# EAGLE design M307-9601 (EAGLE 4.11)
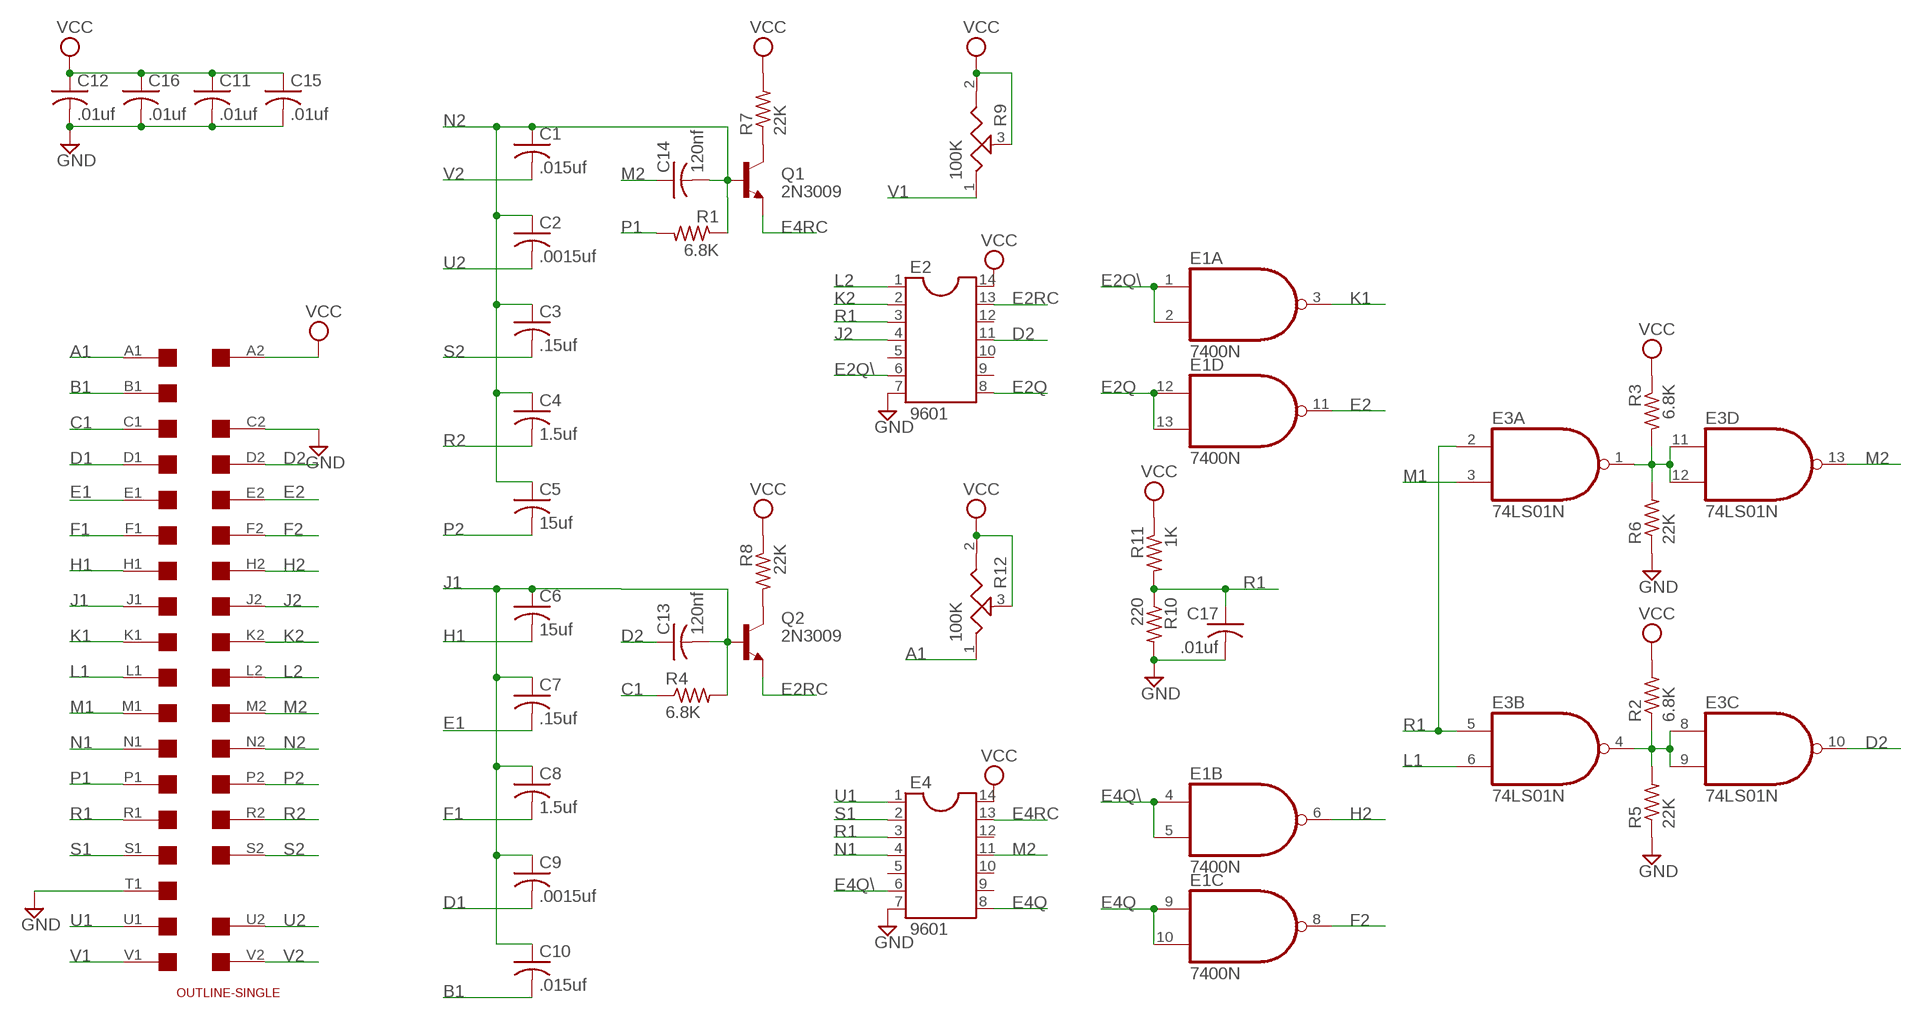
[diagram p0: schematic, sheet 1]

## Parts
C1  .015uf  C-US150-054X183  [C150-054X183]
C2  .0015uf  C-US050-025X075  [C050-025X075]
C3  .15uf  C-US102-043X133  [C102-043X133]
C4  1.5uf  C-US150-054X183  [C150-054X183]
C5  15uf  C-US150-054X183  [C150-054X183]
C6  15uf  C-US150-054X183  [C150-054X183]
C7  .15uf  C-US102-043X133  [C102-043X133]
C8  1.5uf  C-US150-054X183  [C150-054X183]
C9  .0015uf  C-US050-025X075  [C050-025X075]
C10  .015uf  C-US150-054X183  [C150-054X183]
C11  .01uf  C-US050-025X075  [C050-025X075]
C12  .01uf  C-US050-025X075  [C050-025X075]
C13  120nf  C-US075-032X103  [C075-032X103]
C14  120nf  C-US075-032X103  [C075-032X103]
C15  .01uf  C-US050-025X075  [C050-025X075]
C16  .01uf  C-US050-025X075  [C050-025X075]
C17  .01uf  C-US050-025X075  [C050-025X075]
E1  7400N  [DIL14]
E2  9601  DIL14  [DIL14]
E3  74LS01N  [DIL14]
E4  9601  DIL14  [DIL14]
Q1  2N3009  2N3019-NPN-TO39-EBC  [TO39]
Q2  2N3009  2N3019-NPN-TO39-EBC  [TO39]
R1  6.8K  R-US_0207/10  [0207/10]
R2  6.8K  R-US_0207/10  [0207/10]
R3  6.8K  R-US_0207/10  [0207/10]
R4  6.8K  R-US_0207/10  [0207/10]
R5  22K  R-US_0207/10  [0207/10]
R6  22K  R-US_0207/10  [0207/10]
R7  22K  R-US_0207/10  [0207/10]
R8  22K  R-US_0207/10  [0207/10]
R9  100K  POTUS-TRIM  [PT-SPIN]
R10  220  R-US_0207/10  [0207/10]
R11  1K  R-US_0207/10  [0207/10]
R12  100K  POTUS-TRIM  [PT-SPIN]
U$1  OUTLINE-SINGLE  [SINGLE]
U$4  SINGLE  [EDGE-CON2]

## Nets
A1: R12.1 U$4.A1
B1: C10.2 U$4.B1
C1: R4.1 U$4.C1
D1: C9.2 U$4.D1
D2: C13.1 E2.11 E3.10(C:O) U$4.D2
E1: C7.2 U$4.E1
E2: E1.11(D:O) U$4.E2
E2Q: E1.12(D:I0) E1.13(D:I1) E2.8
E2Q\: E1.1(A:I0) E1.2(A:I1) E2.6
E2RC: E2.13 Q2.1(E)
E4Q: E1.9(C:I0) E1.10(C:I1) E4.8
E4Q\: E1.4(B:I0) E1.5(B:I1) E4.6
E4RC: E4.13 Q1.1(E)
F1: C8.2 U$4.F1
F2: E1.8(C:O) U$4.F2
GND [power]: C11.2 C12.2 C15.2 C16.2 C17.2 E2.7 E4.7 R5.1 R6.1 R10.2 U$4.C2 U$4.T1
H1: C6.2 U$4.H1
H2: E1.6(B:O) U$4.H2
J1: C6.1 C7.1 C8.1 C9.1 C10.1 C13.2 Q2.2(B) R4.2 U$4.J1
J2: E2.4 U$4.J2
K1: E1.3(A:O) U$4.K1
K2: E2.2 U$4.K2
L1: E3.6(B:I1) U$4.L1
L2: E2.1 U$4.L2
M1: E3.3(A:I1) U$4.M1
M2: C14.1 E3.13(D:O) E4.11 U$4.M2
N1: E4.4 U$4.N1
N2: C1.1 C2.1 C3.1 C4.1 C5.1 C14.2 Q1.2(B) R1.1 U$4.N2
N$1: Q1.3(C) R7.1
N$2: E3.4(B:O) E3.8(C:I0) E3.9(C:I1) R2.1 R5.2
N$3: Q2.3(C) R8.2
N$5: E3.1(A:O) E3.11(D:I0) E3.12(D:I1) R3.2 R6.2
P1: R1.2 U$4.P1
P2: C5.2 U$4.P2
R1: C17.1 E2.3 E3.2(A:I0) E3.5(B:I0) E4.3 R10.1 R11.2 U$4.R1
R2: C4.2 U$4.R2
S1: E4.2 U$4.S1
S2: C3.2 U$4.S2
U1: E4.1 U$4.U1
U2: C2.2 U$4.U2
V1: R9.1 U$4.V1
V2: C1.2 U$4.V2
VCC [power]: C11.1 C12.1 C15.1 C16.1 E2.14 E4.14 R2.2 R3.1 R7.2 R8.1 R9.2 R9.3 R11.1 R12.2 R12.3 U$4.A2
Unconnected: E2.5 E2.9 E2.10 E2.12 E4.5 E4.9 E4.10 E4.12 U$4.B2 U$4.T2

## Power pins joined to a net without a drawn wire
GND: E1.7(P:GND) E3.7(P:GND)
VCC: E1.14(P:VCC) E3.14(P:VCC)

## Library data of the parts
C1-C17 = rcl:C-US: CAPACITOR, American symbol
E1 = 74xx-us:74*00: Quad 2-input NAND gate
E2 E4 = ic-package:DIL14: Dual In Line
E3 = 74xx-us:74*01: Quad 2-input NAND gate, open collector
Q1 Q2 = transistor:*-NPN-: NPN Transistror
R1-R8 R10 R11 = rcl:R-US_: RESISTOR, American symbol
R9 R12 = discrete:POTUS-TRIM
U$1 = dec-con:OUTLINE-*: Board outlines for DEC boards.
U$4 = dec-con:SINGLE: Single-Height DEC board

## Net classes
1 power: width 0.508 mm, drill 0.508 mm

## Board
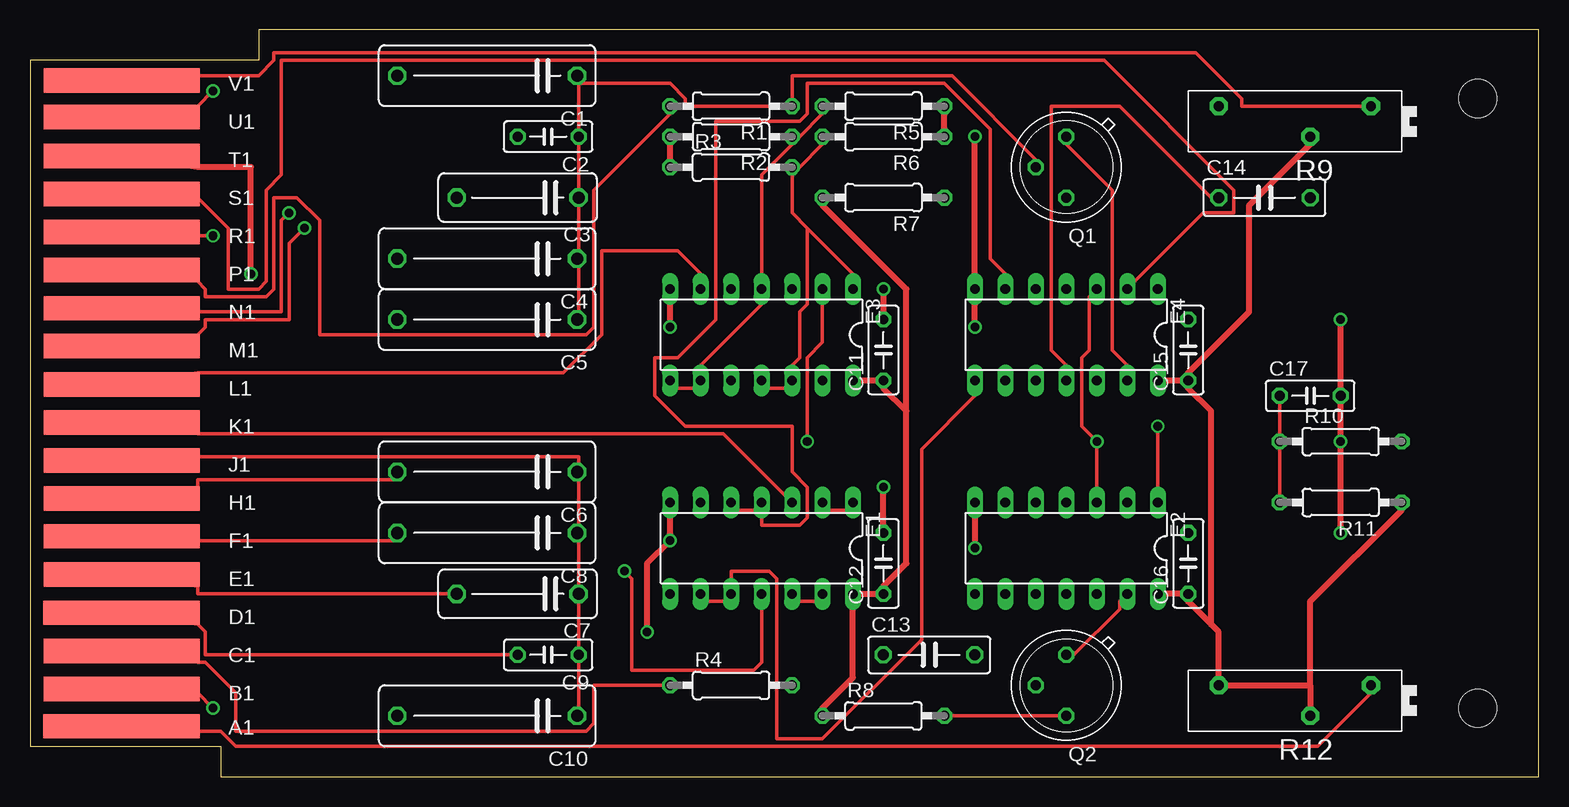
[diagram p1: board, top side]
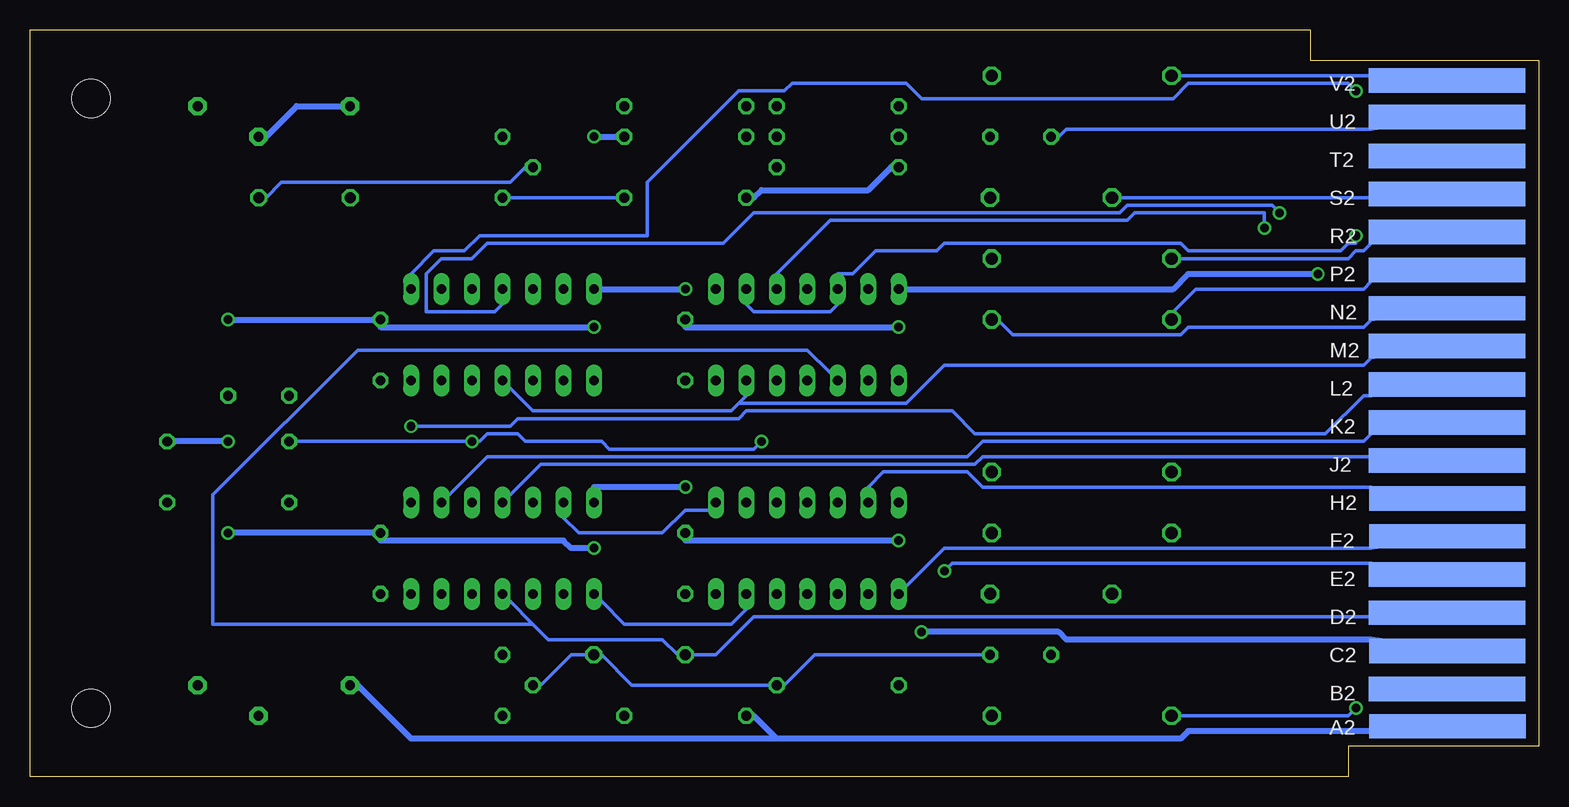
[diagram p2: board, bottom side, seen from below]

Size 125.73 x 62.23 mm. Coordinates in mm from the lower left corner, seen from the top.
Copper layers (1*16): Top 0.035mm / dielectric 1.5mm / Bottom 0.035mm
Design rules "10mils": minimum track width 12mil, minimum drill 28mil, track to track 10mil, track to pad 10mil, pad to pad 10mil, via to via 10mil, smd to smd 10mil, copper to edge 25mil, drill to drill 10mil, minimum pad ring 10mil, minimum via ring 8mil, stop-mask expansion 0mil, vias tented up to drill 0mil, thermal gap 10mil

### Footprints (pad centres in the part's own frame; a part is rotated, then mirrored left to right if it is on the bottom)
C150-054X183 = drill 1.016 octagon: 1 -7.493,0; 2 7.493,0
C050-025X075 = drill 0.813 octagon: 1 -2.54,0; 2 2.54,0
C102-043X133 = drill 1.016 octagon: 1 -5.08,0; 2 5.08,0
C075-032X103 = drill 0.914 octagon: 1 -3.81,0; 2 3.81,0
DIL14 = drill 0.813 long: 1 -7.62,-3.81; 2 -5.08,-3.81; 3 -2.54,-3.81; 4 0,-3.81; 5 2.54,-3.81; 6 5.08,-3.81; 7 7.62,-3.81; 8 7.62,3.81; 9 5.08,3.81; 10 2.54,3.81; 11 0,3.81; 12 -2.54,3.81; 13 -5.08,3.81; 14 -7.62,3.81
TO39 = drill 0.813 octagon: 1 0,-2.54; 2 2.54,0; 3 0,2.54
0207/10 = drill 0.813 octagon: 1 -5.08,0; 2 5.08,0
PT-SPIN = drill 0.813 pad 1.524 octagon: 1 -6.35,-1.27; 2 6.35,-1.27; 3 -1.27,1.27
SINGLE = hole 3.175: 120.65,56.515; 120.65,5.715
EDGE-CON2 = smd 13.017 x 2.032: A1 7.633,4.207; B1 7.639,7.327; C1 7.636,10.489; D1 7.633,13.665; E1 7.642,16.84; F1 7.642,20.041; H1 7.642,23.19; J1 7.642,26.34; K1 7.642,29.515; L1 7.642,32.69; M1 7.642,35.89; N1 7.642,39.04; P1 7.642,42.24; R1 7.642,45.39; S1 7.642,48.565; T1 7.642,51.74; U1 7.642,54.966; V1 7.642,58.026 | smd 13.017 x 2.032 bottom: A2 7.614,4.207; B2 7.642,7.328; C2 7.617,10.49; D2 7.642,13.665; E2 7.642,16.84; F2 7.617,20.041; H2 7.617,23.19; J2 7.642,26.34; K2 7.642,29.515; L2 7.642,32.69; M2 7.642,35.89; N2 7.642,39.04; P2 7.642,42.24; R2 7.642,45.39; S2 7.642,48.565; T2 7.642,51.74; U2 7.642,54.966; V2 7.642,58.026

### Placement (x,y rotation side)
C1  38.1,58.42 180 top
C2  43.18,53.34 180 top
C3  40.64,48.26 180 top
C4  38.1,43.18 180 top
C5  38.1,38.1 180 top
C6  38.1,25.4 180 top
C7  40.64,15.24 180 top
C8  38.1,20.32 180 top
C9  43.18,10.16 180 top
C10  38.1,5.08 180 top
C11  71.12,35.56 90 top
C12  71.12,17.78 90 top
C13  74.93,10.16 0 top
C14  102.87,48.26 0 top
C15  96.52,35.56 90 top
C16  96.52,17.78 90 top
C17  106.68,31.75 0 top
E1  60.96,19.05 180 top
E2  86.36,19.05 180 top
E3  60.96,36.83 180 top
E4  86.36,36.83 180 top
Q1  86.36,50.8 180 top
Q2  86.36,7.62 180 top
R1  58.42,55.88 180 top
R2  58.42,53.34 180 top
R3  58.42,50.8 0 top
R4  58.42,7.62 0 top
R5  71.12,55.88 180 top
R6  71.12,53.34 180 top
R7  71.12,48.26 180 top
R8  71.12,5.08 0 top
R9  105.41,54.61 180 top
R10  109.22,27.94 0 top
R11  109.22,22.86 180 top
R12  105.41,6.35 180 top
U$1  0,0 0 top
U$4  0,0 0 top

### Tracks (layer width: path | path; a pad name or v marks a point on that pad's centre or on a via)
A1
  Top 0.305: R12.1 111.76,6.99 107.32,2.54 17.15,2.54 15.88,3.81 13.97,3.81 U$4.A1
B1  (via drill 0.71)
  Top 0.305: v15.24,5.71 13.97,6.99 U$4.B1
  Bottom 0.305: v15.24,5.71 15.88,5.08 30.48,5.08 C10.2
C1
  Top 0.305: R4.1 52.71,7.62 46.99,7.62 46.99,4.45 46.36,3.81 17.15,3.81 17.15,6.99 14.61,9.53 13.97,9.53 U$4.C1
D1
  Top 0.305: C9.2 40.01,10.16 14.61,10.16 14.61,12.06 13.97,12.7 U$4.D1
D2
  Bottom 0.305: 83.82,12.7 82.55,11.43 73.03,11.43 71.76,10.16 C13.1 70.49,10.16 68.58,10.16 65.41,13.34 13.97,13.34 U$4.D2 | 83.82,12.7 85.73,14.61 E2.11 | 83.82,12.7 110.49,12.7 110.49,23.5 98.43,35.56 60.96,35.56 59.06,33.66 E3.10
E1
  Top 0.305: C7.2 34.93,15.24 13.97,15.24 13.97,15.88 U$4.E1
E2  (via drill 0.71)
  Top 0.305: v49.53,17.14 50.17,16.51 50.17,8.89 60.33,8.89 60.96,9.53 60.96,13.97 E1.11
  Bottom 0.305: v49.53,17.14 48.9,17.78 13.97,17.78 U$4.E2
E2Q
  Top 0.305: E1.12 64.14,14.61 65.41,14.61 E1.13
  Bottom 0.305: E2.8 78.11,14.61 76.2,12.7 67.31,12.7 66.04,13.97 E1.13
E2Q\
  Top 0.305: E1.2 66.68,22.23 67.95,22.23 E1.1
  Bottom 0.305: E2.6 81.28,21.59 80.01,20.32 73.03,20.32 71.12,22.23 69.22,22.23 E1.1
E2RC
  Top 0.305: Q2.1 87,10.16 90.81,13.97 90.81,14.61 E2.13
E4Q
  Top 0.305: E1.9 56.52,14.61 57.79,14.61 E1.10 58.42,16.51 58.42,17.14 61.6,17.14 62.23,16.51 62.23,3.17 66.04,3.17 74.3,11.43 74.3,27.3 78.74,31.75 E4.8
E4Q\
  Top 0.305: E1.5 59.06,22.23 60.33,22.23 E1.4 60.96,21.59 60.96,20.95 64.14,20.95 64.77,21.59 64.77,24.13 63.5,25.4 63.5,29.21 54.61,29.21 52.07,31.75 52.07,34.92 53.98,34.92 57.15,38.1 57.15,54.61 64.14,54.61 64.77,55.24 64.77,57.78 76.2,57.78 80.01,53.98 80.01,43.18 81.28,41.91 E4.6
E4RC
  Top 0.305: E4.13 91.44,34.29 90.17,35.56 90.17,48.9 86.36,52.7 Q1.1
F1
  Top 0.305: C8.2 30.48,19.68 13.97,19.68 U$4.F1
F2
  Bottom 0.305: E1.8 52.71,15.88 49.53,19.05 13.97,19.05 U$4.F2
GND  (via drill 0.71)
  Top 0.508: v71.12,24.13 71.12,20.95 C12.2 | v51.44,12.06 51.44,17.78 v53.34,19.68 53.34,21.59 E1.7 | v109.22,20.32 v109.22,27.94 109.22,31.11 C17.2 109.22,32.38 v109.22,38.1 | R6.1 76.2,53.98 76.2,55.24 R5.1 | v71.12,40.64 71.12,38.73 C11.2 | v53.34,37.47 53.34,39.37 E3.7 | v78.74,53.34 78.74,41.91 E4.7 78.74,39.37 v78.74,37.47 | v18.42,41.91 18.42,50.8 13.97,50.8 U$4.T1 | v78.74,19.05 78.74,21.59 E2.7
  Bottom 0.508: v71.12,24.13 78.74,24.13 E2.7 | v51.44,12.06 40.01,12.06 39.37,11.43 13.97,11.43 U$4.C2 | v53.34,19.68 71.12,19.68 C12.2 | v109.22,20.32 97.16,20.32 C16.2 96.52,19.68 81.28,19.68 80.65,19.05 v78.74,19.05 | v109.22,38.1 97.16,38.1 C15.2 96.52,37.47 v78.74,37.47 | v109.22,27.94 113.67,27.94 R10.2 | v71.12,40.64 78.11,40.64 E4.7 | v53.34,37.47 71.12,37.47 C11.2 | v78.74,53.34 76.84,53.34 R6.1 | v18.42,41.91 29.21,41.91 30.48,40.64 52.71,40.64 E3.7
H1
  Top 0.305: C6.2 30.48,24.77 13.97,24.77 13.97,24.13 U$4.H1
H2
  Bottom 0.305: E1.6 55.88,24.13 54.61,25.4 47.63,25.4 46.36,24.13 13.97,24.13 U$4.H2
J1
  Top 0.305: C10.1 45.72,5.71 45.72,9.53 C9.1 45.72,10.79 45.72,14.61 C7.1 45.72,15.88 45.72,19.68 C8.1 45.72,20.95 45.72,24.77 C6.1 45.72,26.04 45.72,26.67 13.97,26.67 U$4.J1
  Bottom 0.305: Q2.2 83.19,7.62 80.65,10.16 79.38,10.16 C13.2 78.11,10.16 75.57,7.62 64.14,7.62 R4.2 62.87,7.62 60.33,10.16 46.36,10.16 C9.1
J2
  Bottom 0.305: E2.4 85.73,23.5 83.19,26.04 46.99,26.04 46.36,26.67 13.97,26.67 U$4.J2
K1
  Top 0.305: E1.3 62.87,23.5 57.79,28.57 13.97,28.57 U$4.K1
K2
  Bottom 0.305: E2.2 90.81,23.5 87.63,26.67 47.63,26.67 46.36,27.94 14.61,27.94 13.97,28.57 U$4.K2
L1
  Top 0.305: E3.6 55.88,41.91 53.98,43.81 47.63,43.81 47.63,36.83 44.45,33.66 13.97,33.66 U$4.L1
L2  (via drill 0.71)
  Top 0.305: v93.98,29.21 93.98,24.13 E2.1
  Bottom 0.305: v93.98,29.21 85.73,29.21 85.09,29.84 66.68,29.84 66.04,30.48 48.9,30.48 46.99,28.57 17.78,28.57 14.61,31.75 13.97,31.75 U$4.L2
M1  (via drill 0.71)
  Top 0.305: v22.86,45.72 21.59,44.45 21.59,38.1 14.61,38.1 14.61,37.47 13.97,36.83 U$4.M1
  Bottom 0.305: v22.86,45.72 22.86,46.99 33.66,46.99 34.29,46.35 59.06,46.35 63.5,41.91 E3.3
M2
  Top 0.305: C14.1 98.43,48.26 90.81,55.88 85.09,55.88 85.09,35.56 86.36,34.29 E4.11
  Bottom 0.305: 66.68,31.11 67.31,30.48 83.82,30.48 85.73,32.38 E4.11 | 66.68,31.11 66.04,31.75 E3.13 | 66.68,31.11 52.71,31.11 49.53,34.29 14.61,34.29 13.97,34.92 U$4.M2
N1  (via drill 0.71)
  Top 0.305: v21.59,46.99 20.96,46.35 20.96,38.73 13.97,38.73 U$4.N1
  Bottom 0.305: v21.59,46.99 22.23,47.62 34.29,47.62 34.93,46.99 65.41,46.99 67.95,44.45 87.63,44.45 88.9,43.18 91.44,43.18 92.71,41.91 92.71,38.73 87,38.73 86.36,39.37 E4.4
N2
  Top 0.305: C5.1 45.72,38.73 45.72,42.55 C4.1 45.72,43.81 45.72,47.62 C3.1 45.72,48.9 45.72,52.7 C2.1 45.72,53.98 45.72,57.78 | 45.72,57.78 53.34,57.78 54.61,56.52 54.61,55.88 62.87,55.88 R1.1 63.5,56.52 63.5,58.42 76.84,58.42 83.82,51.44 Q1.2 | 45.72,57.78 C1.1 45.72,57.78
  Bottom 0.305: Q1.2 84.46,50.8 85.73,49.53 104.78,49.53 106.05,48.26 C14.2 | U$4.N2 13.97,38.1 14.61,37.47 29.21,37.47 29.85,36.83 43.82,36.83 45.09,38.1 C5.1
N$1
  Bottom 0.305: R7.1 76.84,48.26 85.73,48.26 Q1.3
N$2
  Top 0.305: R5.2 66.04,55.24 64.14,53.34 R2.1 63.5,52.7 60.96,50.16 60.96,41.91 E3.4 60.96,39.37 55.88,34.29 E3.9 55.25,32.38 53.98,32.38 E3.8
N$3
  Top 0.305: R8.2 76.84,5.08 85.73,5.08 Q2.3
N$5
  Top 0.305: E3.11 61.6,32.38 62.87,32.38 E3.12 63.5,34.29 64.14,34.92 64.14,38.73 64.77,39.37 64.77,45.72 | 64.77,45.72 63.5,46.99 63.5,50.16 R3.2 64.14,50.8 66.04,52.7 R6.2 | 64.77,45.72 68.58,41.91 E3.1
P1
  Top 0.305: R1.2 53.34,55.24 46.99,48.9 46.99,37.47 46.36,36.83 24.13,36.83 24.13,46.35 22.23,48.26 20.32,48.26 20.32,40.64 19.69,40.01 14.61,40.01 14.61,40.64 13.97,41.27 U$4.P1
P2
  Bottom 0.305: C5.2 30.48,38.73 28.58,40.64 14.61,40.64 13.97,41.27 U$4.P2
R1  (via drill 0.71)
  Top 0.305: E2.3 88.9,24.13 v88.9,27.94 87.63,29.21 87.63,34.92 88.27,35.56 88.27,40.01 E4.3 | R11.2 104.14,23.5 104.14,27.3 R10.1 104.14,28.57 104.14,31.11 C17.1 | v15.24,45.09 13.97,45.09 U$4.R1 | v64.77,27.94 64.77,34.92 66.04,36.2 66.04,39.37 E3.2
  Bottom 0.305: R10.1 103.51,27.94 v88.9,27.94 88.27,27.94 87.63,28.57 85.09,28.57 84.46,27.94 78.11,27.94 77.47,27.3 65.41,27.3 v64.77,27.94 | v15.24,45.09 15.24,44.45 15.88,44.45 16.51,43.81 29.21,43.81 29.85,44.45 49.53,44.45 50.17,43.81 55.25,43.81 57.15,41.91 58.42,41.91 E3.5 58.42,39.37 59.06,38.73 65.41,38.73 66.04,39.37 E3.2
R2
  Bottom 0.305: C4.2 30.48,43.18 15.88,43.18 15.24,43.81 14.61,43.81 13.97,44.45 U$4.R2
S1
  Top 0.305: E4.2 92.08,41.27 97.79,46.99 100.33,46.99 100.33,48.9 89.54,59.69 20.96,59.69 20.96,50.16 19.69,48.9 19.69,41.27 19.05,40.64 16.51,40.64 16.51,45.72 13.97,48.26 U$4.S1
S2
  Bottom 0.305: C3.2 34.93,48.26 13.97,48.26 U$4.S2
U1  (via drill 0.71)
  Top 0.305: v15.24,57.15 13.97,55.88 U$4.U1
  Bottom 0.305: v15.24,57.15 15.88,57.78 29.21,57.78 30.48,56.52 51.44,56.52 52.71,57.78 62.23,57.78 62.87,57.15 66.68,57.15 74.3,49.53 74.3,45.09 88.27,45.09 89.54,43.81 92.08,43.81 93.98,41.91 E4.1
U2
  Bottom 0.305: C2.2 40.01,53.34 39.37,53.98 13.97,53.98 U$4.U2
V1
  Top 0.305: R9.1 111.13,55.88 100.97,55.88 100.97,56.52 97.16,60.33 20.32,60.33 20.32,59.69 19.05,58.42 13.97,58.42 U$4.V1
V2
  Bottom 0.305: C1.2 30.48,58.42 13.97,58.42 U$4.V2
VCC
  Top 0.508: E4.14 94.62,33.02 95.89,33.02 C15.1 | E2.14 94.62,15.24 95.89,15.24 C16.1 96.52,14.61 98.43,12.7 | 106.68,7.62 106.68,5.71 R12.3 | 106.68,7.62 106.68,14.61 114.3,22.23 R11.1 | 106.68,7.62 99.7,7.62 R12.2 99.06,8.26 99.06,12.06 98.43,12.7 | 98.43,12.7 98.43,30.48 96.52,32.38 C15.1 | R9.3 106.68,52.7 101.6,47.62 101.6,38.73 96.52,33.66 C15.1 | R3.1 53.34,51.44 53.34,52.7 R2.2 | E3.14 69.22,33.02 70.49,33.02 C11.1 71.12,32.38 73.03,30.48 | R8.1 66.04,5.71 68.58,8.26 68.58,13.97 E1.14 69.22,15.24 70.49,15.24 C12.1 71.12,15.88 73.03,17.78 73.03,30.48 | 73.03,30.48 73.03,40.64 66.04,47.62 R7.2
  Bottom 0.508: R9.3 106.05,53.34 103.51,55.88 99.7,55.88 R9.2 | R7.2 65.41,48.26 64.77,48.9 55.88,48.9 53.98,50.8 R3.1 | 63.5,3.17 29.85,3.17 29.21,3.81 13.97,3.81 U$4.A2 | 63.5,3.17 65.41,5.08 R8.1 | 63.5,3.17 93.98,3.17 98.43,7.62 R12.2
